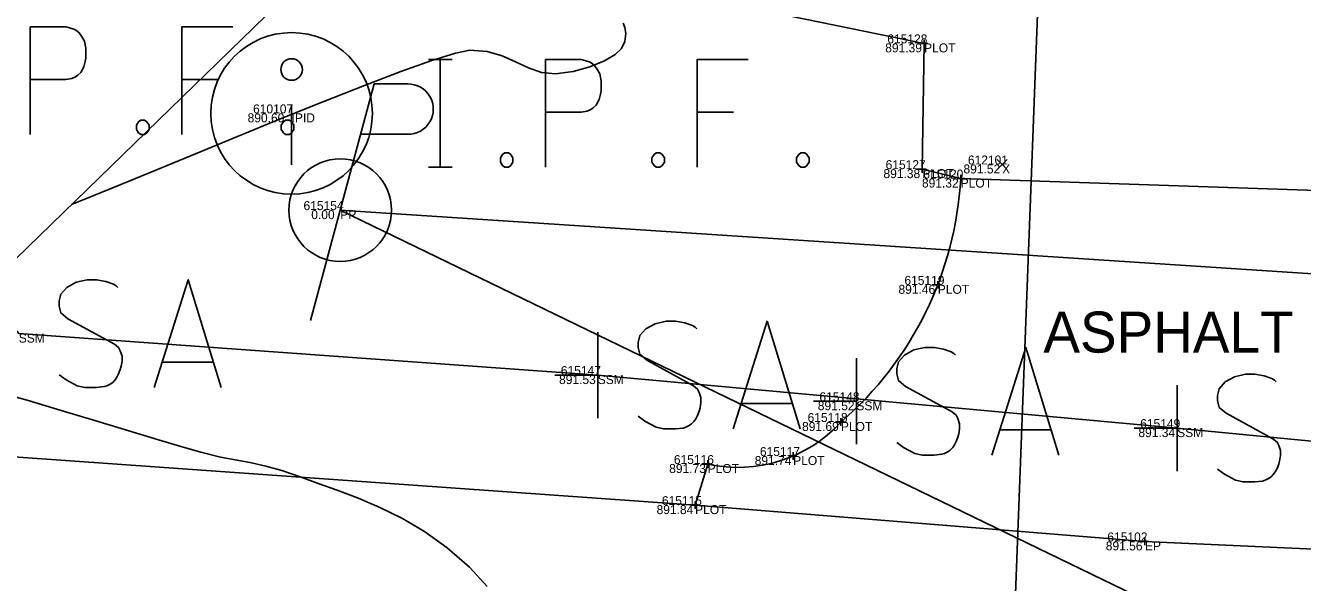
# Model space of a CAD drawing. Extents: x 1957117 to 1971063, y 701601 to 715861.
# Drawn here: x 1962659.74 to 1962709.51, y 702014.33 to 702036.06 of the extents above; entities that cross this region are included whole.
import ezdxf

# ---------------------------------------------------------------- set-up
doc = ezdxf.new("R2010")
doc.units = 0
for name, color, linetype in [('AP_X_Lights', 7, 'Continuous'), ('DT_X_Break_Line', 7, 'Continuous'), ('DT_X_Contour_Minor', 7, 'Continuous'), ('DT_X_TIN_Hull', 7, 'Continuous'), ('GE_P_CL_50', 7, 'Continuous'), ('GE_X_CL_20', 7, 'Continuous'), ('PM_P_Transverse_Line', 7, 'Continuous'), ('PV_P_Drive', 7, 'Continuous'), ('PV_P_Shoulder', 7, 'Continuous'), ('PV_X_Bikeway', 7, 'Continuous'), ('RS_Raster1', 7, 'Continuous'), ('SC_Scratch1', 7, 'Continuous'), ('SC_Scratch2', 7, 'Continuous'), ('SC_Shading1', 7, 'Continuous'), ('SC_Shading3', 7, 'Continuous'), ('SC_Shading4', 7, 'Continuous'), ('SC_Shading5', 7, 'Continuous')]:
    doc.layers.add(name, color=color, linetype=linetype)

msp = doc.modelspace()

# ---------------------------------------------------------------- linework, layer by layer
at = {"layer": 'AP_X_Lights'}
for p, q in [((1962697.609, 702030.443), (1962697.997, 702030.833)), ((1962697.609, 702030.833), (1962697.997, 702030.443))]:
    msp.add_line(p, q, dxfattribs=at)
at = {"layer": 'DT_X_Contour_Minor'}
for points in [[(1962683.041, 702036.148), (1962683.105, 702035.983), (1962683.138, 702035.744), (1962683.098, 702035.441), (1962682.97, 702035.162), (1962682.726, 702034.934), (1962682.301, 702034.683), (1962681.74, 702034.448), (1962681.091, 702034.265), (1962680.401, 702034.173), (1962679.852, 702034.227), (1962679.343, 702034.404), (1962678.843, 702034.641), (1962678.317, 702034.877), (1962677.733, 702035.049), (1962677.06, 702035.096), (1962676.496, 702034.981), (1962675.579, 702034.693), (1962674.374, 702034.262), (1962672.949, 702033.721), (1962671.368, 702033.098), (1962669.699, 702032.426), (1962668.007, 702031.735), (1962666.359, 702031.056), (1962664.821, 702030.419), (1962663.46, 702029.856), (1962662.34, 702029.397), (1962661.53, 702029.073)], [(1962683.041, 702036.148), (1962683.105, 702035.983), (1962683.138, 702035.744), (1962683.098, 702035.441), (1962682.97, 702035.162), (1962682.726, 702034.934), (1962682.301, 702034.683), (1962681.74, 702034.448), (1962681.091, 702034.265), (1962680.401, 702034.173), (1962679.852, 702034.227), (1962679.343, 702034.404), (1962678.843, 702034.641), (1962678.317, 702034.877), (1962677.733, 702035.049), (1962677.06, 702035.096), (1962676.496, 702034.981), (1962675.579, 702034.693), (1962674.374, 702034.262), (1962672.949, 702033.721), (1962671.368, 702033.098), (1962669.699, 702032.426), (1962668.007, 702031.735), (1962666.359, 702031.056), (1962664.821, 702030.419), (1962663.46, 702029.856), (1962662.34, 702029.397), (1962661.53, 702029.073)], [(1962677.732, 702014.178), (1962677.051, 702014.927), (1962676.181, 702015.688), (1962675.294, 702016.321), (1962674.405, 702016.843), (1962673.53, 702017.274), (1962672.684, 702017.631), (1962671.883, 702017.932), (1962671.142, 702018.195), (1962670.478, 702018.438), (1962669.733, 702018.7), (1962669.112, 702018.873), (1962668.551, 702018.993), (1962667.983, 702019.099), (1962667.344, 702019.226), (1962666.569, 702019.411), (1962665.887, 702019.604), (1962664.929, 702019.891), (1962663.768, 702020.246), (1962662.478, 702020.64), (1962661.131, 702021.047), (1962659.801, 702021.438), (1962658.561, 702021.786)], [(1962677.732, 702014.178), (1962677.051, 702014.927), (1962676.181, 702015.688), (1962675.294, 702016.321), (1962674.405, 702016.843), (1962673.53, 702017.274), (1962672.684, 702017.631), (1962671.883, 702017.932), (1962671.142, 702018.195), (1962670.478, 702018.438), (1962669.733, 702018.7), (1962669.112, 702018.873), (1962668.551, 702018.993), (1962667.983, 702019.099), (1962667.344, 702019.226), (1962666.569, 702019.411), (1962665.887, 702019.604), (1962664.929, 702019.891), (1962663.768, 702020.246), (1962662.478, 702020.64), (1962661.131, 702021.047), (1962659.801, 702021.438), (1962658.561, 702021.786)]]:
    msp.add_lwpolyline(points, dxfattribs=at)
at = {"layer": 'DT_X_TIN_Hull'}
msp.add_lwpolyline([(1962657.931, 702308.011), (1962655.854, 702258.355), (1962653.64, 702207.97), (1962651.503, 702157.712), (1962649.771, 702107.746), (1962674.688, 702087.643), (1962671.405, 702038.683), (1962651.95, 702019.751), (1962598.276, 702023.522), (1962596.236, 701997.877), (1962651.443, 701993.881), (1962750.651, 701987.35), (1962803.275, 701984.672), (1962804.883, 701997.219), (1962805.914, 702009.441), (1962753.632, 702013.572), (1962730.2, 702029.616), (1962722.307, 702088.916), (1962751.157, 702101.248), (1962753.404, 702150.955), (1962757.576, 702251.621), (1962759.026, 702351.713)], dxfattribs=at)
at = {"layer": 'GE_P_CL_50'}
msp.add_lwpolyline([(1962651.369, 702033.935), (1962659.476, 702024.04), (1962682.043, 702022.422), (1962704.627, 702020.353), (1962717.128, 702019.14), (1962723.885, 702018.961)], dxfattribs=at)
at = {"layer": 'GE_X_CL_20'}
msp.add_lwpolyline([(1962741.373, 703141.619), (1962697.729, 701998.272)], dxfattribs=at)
at = {"layer": 'PM_P_Transverse_Line'}
for p, q in [((1962673.326, 702033.78), (1962670.854, 702024.549)), ((1962673.326, 702033.78), (1962674.634, 702033.78)), ((1962672.8, 702031.819), (1962674.634, 702031.819))]:
    msp.add_line(p, q, dxfattribs=at)
msp.add_circle((1962672.008, 702028.857), 2, dxfattribs=at)
msp.add_arc((1962674.653, 702032.799), 0.981, 268.8767, 91.1233, dxfattribs=at)
at = {"layer": 'PV_P_Drive'}
for p, q in [((1962694.618, 702035.361), (1962694.91, 702035.361)), ((1962694.764, 702035.507), (1962694.764, 702035.215)), ((1962694.764, 702035.361), (1962694.764, 702035.361)), ((1962694.695, 702030.602), (1962694.695, 702030.31)), ((1962694.549, 702030.456), (1962694.841, 702030.456)), ((1962694.695, 702030.456), (1962694.695, 702030.456)), ((1962696.045, 702030.089), (1962696.337, 702030.089)), ((1962696.191, 702030.235), (1962696.191, 702029.943)), ((1962696.191, 702030.089), (1962696.191, 702030.089)), ((1962695.151, 702025.943), (1962695.443, 702025.943)), ((1962695.297, 702026.089), (1962695.297, 702025.797)), ((1962695.297, 702025.943), (1962695.297, 702025.943)), ((1962691.522, 702020.738), (1962691.522, 702020.446)), ((1962691.376, 702020.592), (1962691.668, 702020.592)), ((1962691.522, 702020.592), (1962691.522, 702020.592)), ((1962689.515, 702019.263), (1962689.807, 702019.263)), ((1962689.661, 702019.409), (1962689.661, 702019.117)), ((1962689.661, 702019.263), (1962689.661, 702019.263)), ((1962686.184, 702018.952), (1962686.476, 702018.952)), ((1962686.33, 702019.098), (1962686.33, 702018.806)), ((1962686.33, 702018.952), (1962686.33, 702018.952)), ((1962685.694, 702017.349), (1962685.986, 702017.349)), ((1962685.84, 702017.495), (1962685.84, 702017.203)), ((1962685.84, 702017.349), (1962685.84, 702017.349)), ((1962703.228, 702015.933), (1962703.52, 702015.933)), ((1962703.374, 702016.079), (1962703.374, 702015.787)), ((1962703.374, 702015.933), (1962703.374, 702015.933))]:
    msp.add_line(p, q, dxfattribs=at)
at = {"layer": 'PV_X_Bikeway'}
msp.add_lwpolyline([(1962713.167, 702029.519), (1962715.026, 702029.838), (1962713.685, 702031.456), (1962716.601, 702087.336), (1962682.889, 702088.807), (1962679.07, 702038.576), (1962694.764, 702035.361), (1962694.695, 702030.456), (1962696.191, 702030.089)], dxfattribs=at)
at = {"layer": 'SC_Scratch2'}
for points in [[(1962713.167, 702029.519), (1962696.191, 702030.089)], [(1962686.33, 702018.952), (1962685.84, 702017.349)]]:
    msp.add_lwpolyline(points, dxfattribs=at)
for centre, radius, start, end in [((1962682.688, 702030.831), 13.523, 310.7862, 356.8536), ((1962687.517, 702024.233), 5.413, 257.3319, 317.7277)]:
    msp.add_arc(centre, radius, start, end, dxfattribs=at)
at = {"layer": 'SC_Shading1'}
for p, q in [((1962682.043, 702020.742), (1962682.043, 702024.102)), ((1962692.125, 702019.721), (1962692.125, 702023.081)), ((1962682.043, 702022.422), (1962680.371, 702022.422)), ((1962704.627, 702018.673), (1962704.627, 702022.033)), ((1962692.125, 702021.401), (1962690.453, 702021.401)), ((1962704.627, 702020.353), (1962702.955, 702020.353))]:
    msp.add_line(p, q, dxfattribs=at)
for points in [[(1962663.336, 702025.842), (1962663.27, 702025.908), (1962663.17, 702025.974), (1962662.873, 702026.074), (1962662.509, 702026.14), (1962662.244, 702026.14), (1962662.145, 702026.14), (1962661.715, 702026.041), (1962661.352, 702025.842), (1962661.12, 702025.578), (1962661.054, 702025.313), (1962661.054, 702025.115), (1962661.12, 702024.85), (1962661.384, 702024.619), (1962663.203, 702023.627), (1962663.369, 702023.494), (1962663.435, 702023.362), (1962663.501, 702023.164), (1962663.501, 702022.965), (1962663.468, 702022.767), (1962663.435, 702022.635), (1962663.369, 702022.469), (1962663.302, 702022.337), (1962663.236, 702022.238), (1962663.137, 702022.138), (1962663.038, 702022.072), (1962662.906, 702022.006), (1962662.807, 702021.973), (1962662.509, 702021.94), (1962662.046, 702021.94), (1962661.748, 702022.006), (1962661.318, 702022.238), (1962661.054, 702022.436)], [(1962664.757, 702021.94), (1962666.08, 702026.14), (1962667.37, 702021.94)], [(1962685.903, 702024.224), (1962685.837, 702024.29), (1962685.737, 702024.356), (1962685.44, 702024.456), (1962685.076, 702024.522), (1962684.811, 702024.522), (1962684.712, 702024.522), (1962684.282, 702024.423), (1962683.919, 702024.224), (1962683.687, 702023.96), (1962683.621, 702023.695), (1962683.621, 702023.497), (1962683.687, 702023.232), (1962683.951, 702023.001), (1962685.77, 702022.009), (1962685.936, 702021.876), (1962686.002, 702021.744), (1962686.068, 702021.546), (1962686.068, 702021.347), (1962686.035, 702021.149), (1962686.002, 702021.017), (1962685.936, 702020.851), (1962685.869, 702020.719), (1962685.803, 702020.62), (1962685.704, 702020.52), (1962685.605, 702020.454), (1962685.473, 702020.388), (1962685.374, 702020.355), (1962685.076, 702020.322), (1962684.613, 702020.322), (1962684.315, 702020.388), (1962683.885, 702020.62), (1962683.621, 702020.818)], [(1962687.324, 702020.322), (1962688.647, 702024.522), (1962689.937, 702020.322)], [(1962695.985, 702023.203), (1962695.919, 702023.269), (1962695.819, 702023.335), (1962695.522, 702023.435), (1962695.158, 702023.501), (1962694.893, 702023.501), (1962694.794, 702023.501), (1962694.364, 702023.402), (1962694.001, 702023.203), (1962693.769, 702022.939), (1962693.703, 702022.674), (1962693.703, 702022.476), (1962693.769, 702022.211), (1962694.033, 702021.98), (1962695.852, 702020.988), (1962696.018, 702020.855), (1962696.084, 702020.723), (1962696.15, 702020.525), (1962696.15, 702020.326), (1962696.117, 702020.128), (1962696.084, 702019.996), (1962696.018, 702019.83), (1962695.951, 702019.698), (1962695.885, 702019.599), (1962695.786, 702019.499), (1962695.687, 702019.433), (1962695.555, 702019.367), (1962695.456, 702019.334), (1962695.158, 702019.301), (1962694.695, 702019.301), (1962694.397, 702019.367), (1962693.967, 702019.599), (1962693.703, 702019.797)], [(1962697.406, 702019.301), (1962698.729, 702023.501), (1962700.019, 702019.301)], [(1962667.039, 702022.932), (1962665.088, 702022.932)], [(1962708.487, 702022.155), (1962708.421, 702022.221), (1962708.321, 702022.287), (1962708.024, 702022.387), (1962707.66, 702022.453), (1962707.395, 702022.453), (1962707.296, 702022.453), (1962706.866, 702022.354), (1962706.503, 702022.155), (1962706.271, 702021.891), (1962706.205, 702021.626), (1962706.205, 702021.428), (1962706.271, 702021.163), (1962706.535, 702020.932), (1962708.354, 702019.94), (1962708.52, 702019.807), (1962708.586, 702019.675), (1962708.652, 702019.477), (1962708.652, 702019.278), (1962708.619, 702019.08), (1962708.586, 702018.948), (1962708.52, 702018.782), (1962708.453, 702018.65), (1962708.387, 702018.551), (1962708.288, 702018.451), (1962708.189, 702018.385), (1962708.057, 702018.319), (1962707.958, 702018.286), (1962707.66, 702018.253), (1962707.197, 702018.253), (1962706.899, 702018.319), (1962706.469, 702018.551), (1962706.205, 702018.749)], [(1962689.606, 702021.314), (1962687.655, 702021.314)], [(1962699.688, 702020.293), (1962697.737, 702020.293)]]:
    msp.add_lwpolyline(points, dxfattribs=at)
at = {"layer": 'SC_Shading3'}
msp.add_line((1962670.111, 702032.938), (1962670.111, 702030.62), dxfattribs=at)
for points in [[(1962659.924, 702031.807), (1962659.924, 702036.007), (1962661.313, 702036.007), (1962661.458, 702035.974), (1962661.661, 702035.908), (1962661.748, 702035.841), (1962661.834, 702035.775), (1962661.95, 702035.61), (1962662.037, 702035.445), (1962662.095, 702035.18), (1962662.095, 702034.783), (1962662.066, 702034.651), (1962662.008, 702034.453), (1962661.892, 702034.221), (1962661.776, 702034.122), (1962661.69, 702034.056), (1962661.545, 702033.99), (1962661.313, 702033.957), (1962659.924, 702033.957)], [(1962667.824, 702036.007), (1962665.827, 702036.007), (1962665.827, 702031.807)], [(1962675.441, 702034.732), (1962676.367, 702034.732)], [(1962675.904, 702030.532), (1962675.904, 702034.732)], [(1962680.012, 702030.532), (1962680.012, 702034.732), (1962681.401, 702034.732), (1962681.546, 702034.699), (1962681.749, 702034.633), (1962681.836, 702034.566), (1962681.922, 702034.5), (1962682.038, 702034.335), (1962682.125, 702034.17), (1962682.183, 702033.905), (1962682.183, 702033.508), (1962682.154, 702033.376), (1962682.096, 702033.178), (1962681.98, 702032.946), (1962681.864, 702032.847), (1962681.778, 702032.781), (1962681.633, 702032.715), (1962681.401, 702032.682), (1962680.012, 702032.682)], [(1962687.912, 702034.732), (1962685.915, 702034.732), (1962685.915, 702030.532)], [(1962665.827, 702033.957), (1962667.245, 702033.957)], [(1962685.915, 702032.682), (1962687.333, 702032.682)], [(1962664.236, 702032.369), (1962664.38, 702032.369), (1962664.467, 702032.303), (1962664.554, 702032.171), (1962664.554, 702032.005), (1962664.467, 702031.873), (1962664.38, 702031.807), (1962664.236, 702031.807), (1962664.149, 702031.873), (1962664.062, 702032.005), (1962664.062, 702032.171), (1962664.149, 702032.303), (1962664.236, 702032.369)], [(1962669.878, 702032.369), (1962670.023, 702032.369), (1962670.11, 702032.303), (1962670.196, 702032.171), (1962670.196, 702032.005), (1962670.11, 702031.873), (1962670.023, 702031.807), (1962669.878, 702031.807), (1962669.791, 702031.873), (1962669.705, 702032.005), (1962669.705, 702032.171), (1962669.791, 702032.303), (1962669.878, 702032.369)], [(1962678.421, 702031.094), (1962678.566, 702031.094), (1962678.653, 702031.028), (1962678.739, 702030.896), (1962678.739, 702030.73), (1962678.653, 702030.598), (1962678.566, 702030.532), (1962678.421, 702030.532), (1962678.334, 702030.598), (1962678.248, 702030.73), (1962678.248, 702030.896), (1962678.334, 702031.028), (1962678.421, 702031.094)], [(1962684.324, 702031.094), (1962684.468, 702031.094), (1962684.555, 702031.028), (1962684.642, 702030.896), (1962684.642, 702030.73), (1962684.555, 702030.598), (1962684.468, 702030.532), (1962684.324, 702030.532), (1962684.237, 702030.598), (1962684.15, 702030.73), (1962684.15, 702030.896), (1962684.237, 702031.028), (1962684.324, 702031.094)], [(1962689.966, 702031.094), (1962690.111, 702031.094), (1962690.198, 702031.028), (1962690.284, 702030.896), (1962690.284, 702030.73), (1962690.198, 702030.598), (1962690.111, 702030.532), (1962689.966, 702030.532), (1962689.879, 702030.598), (1962689.793, 702030.73), (1962689.793, 702030.896), (1962689.879, 702031.028), (1962689.966, 702031.094)], [(1962675.441, 702030.532), (1962676.367, 702030.532)]]:
    msp.add_lwpolyline(points, dxfattribs=at)
for centre, radius in [((1962670.111, 702032.632), 3.15), ((1962670.111, 702034.343), 0.42)]:
    msp.add_circle(centre, radius, dxfattribs=at)
at = {"layer": 'SC_Shading4'}
for points in [[(1962672.008, 702028.857), (1962780.372, 702021.756)], [(1962672.008, 702028.857), (1962789.593, 701971.83)]]:
    msp.add_lwpolyline(points, dxfattribs=at)
at = {"layer": 'SC_Shading5'}
msp.add_lwpolyline([(1962598.276, 702023.522), (1962651.95, 702019.751), (1962685.84, 702017.349), (1962703.374, 702015.933), (1962722.006, 702015.091), (1962753.632, 702013.572), (1962805.914, 702009.441)], dxfattribs=at)

# ---------------------------------------------------------------- texts
at = {"layer": 'DT_X_Break_Line'}
msp.add_text('ASPHALT', height=1.6, dxfattribs=at).set_placement((1962699.413, 702023.299))
at = {"layer": 'PV_P_Shoulder'}
for s, p in [('891.39', (1962693.249, 702035.011)), ('890.60', (1962668.397, 702032.282)), ('891.52', (1962696.299, 702030.288)), ('891.38', (1962693.18, 702030.106)), ('891.32', (1962694.681, 702029.739)), ('0.00', (1962670.878, 702028.507)), ('891.46', (1962693.765, 702025.593)), ('891.53', (1962680.536, 702022.072)), ('891.52', (1962690.621, 702021.051)), ('891.69', (1962690.007, 702020.242)), ('891.34', (1962703.117, 702020.003)), ('891.74', (1962688.162, 702018.913)), ('891.73', (1962684.828, 702018.602)), ('891.84', (1962684.336, 702016.999)), ('891.56', (1962701.845, 702015.583))]:
    msp.add_text(s, height=0.35, dxfattribs=at).set_placement(p)
at = {"layer": 'RS_Raster1'}
for s, p in [('615128', (1962693.331, 702035.361)), ('610107', (1962668.609, 702032.632)), ('615127', (1962693.265, 702030.456)), ('612101', (1962696.472, 702030.638)), ('615120', (1962694.731, 702030.089)), ('615154', (1962670.575, 702028.857)), ('615119', (1962693.997, 702025.943)), ('615147', (1962680.605, 702022.422)), ('615148', (1962690.684, 702021.401)), ('615118', (1962690.222, 702020.592)), ('615149', (1962703.186, 702020.353)), ('615116', (1962685.011, 702018.952)), ('615117', (1962688.364, 702019.263)), ('615115', (1962684.543, 702017.349)), ('615102', (1962701.908, 702015.933))]:
    msp.add_text(s, height=0.35, dxfattribs=at).set_placement(p)
at = {"layer": 'SC_Scratch1'}
for s, p in [('PLOT', (1962694.764, 702035.011)), ('IPID', (1962670.111, 702032.282)), ('X', (1962697.803, 702030.288)), ('PLOT', (1962694.695, 702030.106)), ('PLOT', (1962696.191, 702029.739)), ('PP', (1962672.008, 702028.507)), ('PLOT', (1962695.297, 702025.593)), ('SSM', (1962659.476, 702023.69)), ('SSM', (1962682.043, 702022.072)), ('SSM', (1962692.125, 702021.051)), ('PLOT', (1962691.522, 702020.242)), ('SSM', (1962704.627, 702020.003)), ('PLOT', (1962689.661, 702018.913)), ('PLOT', (1962686.33, 702018.602)), ('PLOT', (1962685.84, 702016.999)), ('EP', (1962703.374, 702015.583))]:
    msp.add_text(s, height=0.35, dxfattribs=at).set_placement(p)

doc.saveas('drawing.dxf')
